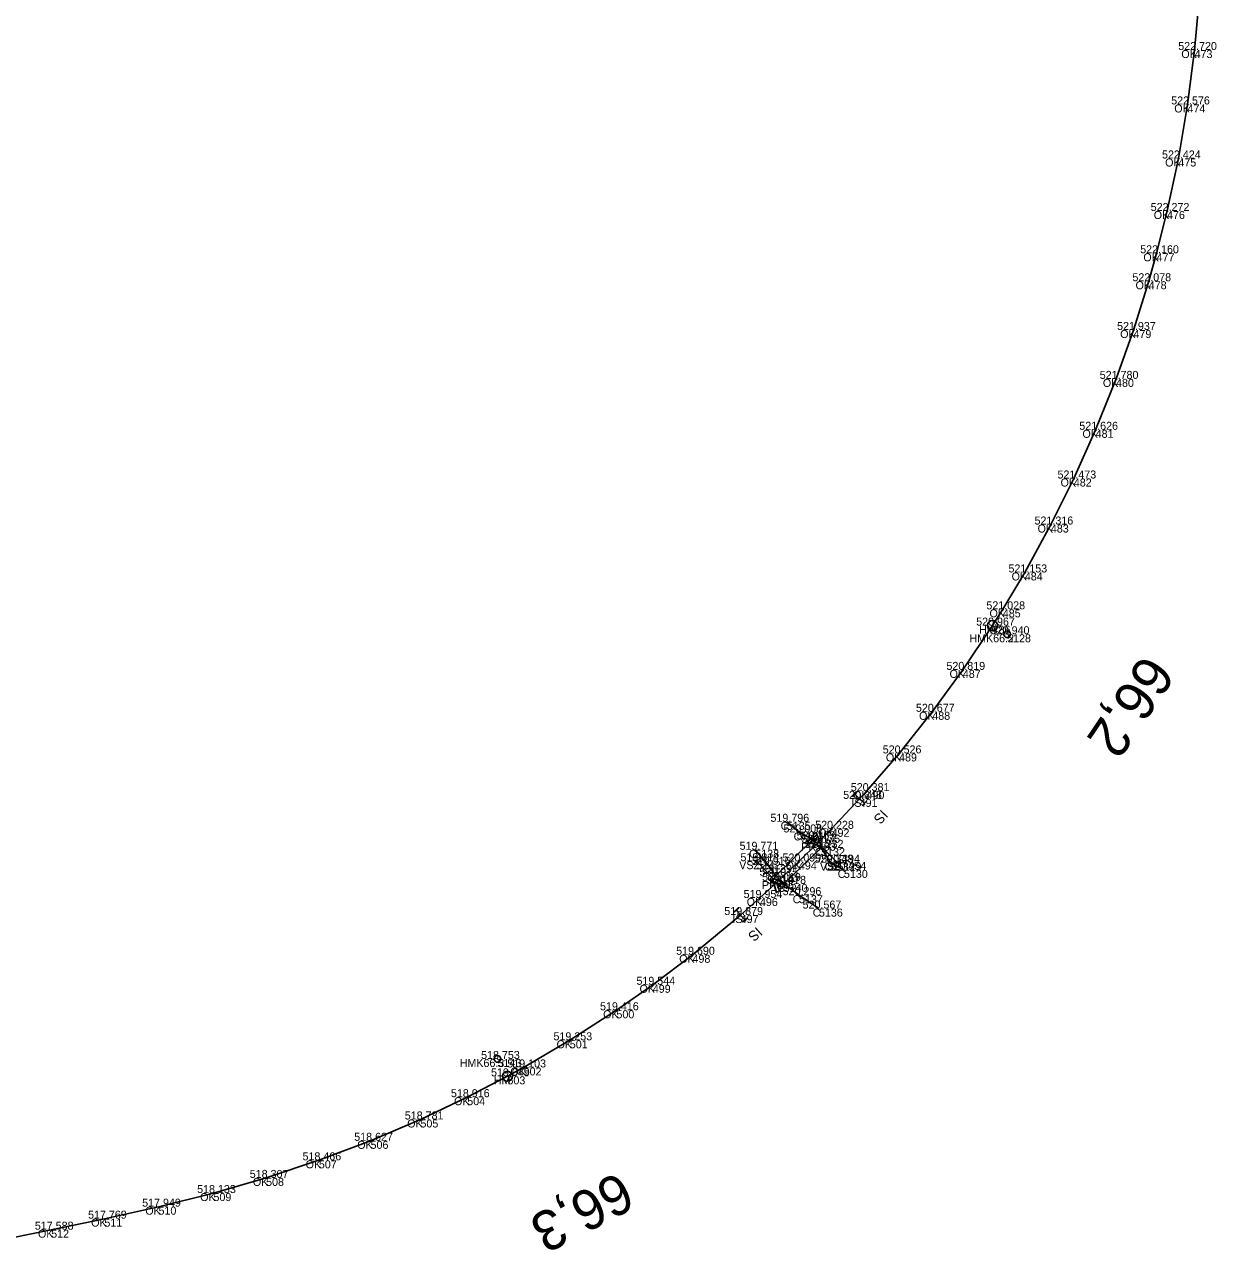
# Model space of a CAD drawing. Extents: x -621782 to -610392, y -1141853 to -1122321.
# Drawn here: x -621330.7 to -621152, y -1123404.2 to -1123220.4 of the extents above; entities that cross this region are included whole.
import ezdxf

# ---------------------------------------------------------------- set-up
doc = ezdxf.new("R2010")
doc.units = 0
for name, color, linetype in [('Vrstva 1', 7, 'Continuous'), ('Vrstva 3', 7, 'Continuous'), ('Vrstva 4', 7, 'Continuous'), ('Vrstva 51', 7, 'Continuous'), ('Vrstva 60', 7, 'Continuous'), ('Vrstva 61', 7, 'Continuous'), ('Vrstva 62', 7, 'Continuous'), ('Vrstva 7', 7, 'Continuous')]:
    doc.layers.add(name, color=color, linetype=linetype)

msp = doc.modelspace()

# ---------------------------------------------------------------- linework, layer by layer
at = {"layer": 'Vrstva 1'}
msp.add_lwpolyline([(-621154.6, -1123216.63), (-621155.27, -1123224.26), (-621156.33, -1123232.42), (-621157.7, -1123240.52), (-621159.4, -1123248.39), (-621160.97, -1123254.73), (-621162.14, -1123258.92), (-621164.43, -1123266.23), (-621167.04, -1123273.56), (-621170.1, -1123281.19), (-621173.37, -1123288.49), (-621176.81, -1123295.39), (-621180.72, -1123302.57), (-621184.02, -1123308.1), (-621185.56, -1123310.54), (-621190.01, -1123317.18), (-621194.59, -1123323.46), (-621199.57, -1123329.7), (-621204.45, -1123335.35), (-621205.49, -1123336.51), (-621209.69, -1123341), (-621211.75, -1123343.09), (-621214.59, -1123345.9), (-621217.64, -1123348.82), (-621220.43, -1123351.37), (-621223.32, -1123353.92), (-621230.54, -1123359.88), (-621236.49, -1123364.38), (-621241.94, -1123368.2), (-621248.93, -1123372.7), (-621255.85, -1123376.77), (-621258.28, -1123378.1), (-621264.3, -1123381.23), (-621271.32, -1123384.57), (-621278.8, -1123387.77), (-621286.55, -1123390.69), (-621294.46, -1123393.33), (-621302.35, -1123395.6), (-621310.59, -1123397.64), (-621318.7, -1123399.44), (-621326.68, -1123401.09), (-621335.56, -1123402.89)], dxfattribs=at)
at = {"layer": 'Vrstva 3'}
for p, q in [((-621205.88, -1123335.46), (-621206.56, -1123336.19)), ((-621204.76, -1123337.19), (-621206.22, -1123335.82)), ((-621204.42, -1123336.82), (-621205.1, -1123337.55)), ((-621223.61, -1123352.84), (-621224.36, -1123353.51)), ((-621222.66, -1123354.67), (-621223.98, -1123353.17)), ((-621222.28, -1123354.34), (-621223.03, -1123355))]:
    msp.add_line(p, q, dxfattribs=at)
at = {"layer": 'Vrstva 4'}
for p, q in [((-621212.26, -1123342.96), (-621212.26, -1123342.47)), ((-621220.32, -1123345.33), (-621221.47, -1123346.38)), ((-621209.33, -1123346.64), (-621208.24, -1123345.53)), ((-621217.6, -1123349.16), (-621217.62, -1123349.65))]:
    msp.add_line(p, q, dxfattribs=at)
for points in [[(-621208.78, -1123346.08), (-621211.26, -1123343.65), (-621213.39, -1123342.95), (-621211.99, -1123341.52), (-621211.26, -1123343.65)], [(-621211.75, -1123343.09), (-621214.59, -1123345.9), (-621217.64, -1123348.82)], [(-621220.9, -1123345.86), (-621218.55, -1123348.42), (-621216.47, -1123349.24), (-621217.94, -1123350.59), (-621218.55, -1123348.42)]]:
    msp.add_lwpolyline(points, dxfattribs=at)
for centre in [(-621212.26, -1123342.71), (-621217.61, -1123349.41)]:
    msp.add_circle(centre, 0.248, dxfattribs=at)
at = {"layer": 'Vrstva 51'}
for points in [[(-621221.12, -1123344.14), (-621219.19, -1123346.4), (-621218.05, -1123348.03), (-621212.48, -1123342.58), (-621214.45, -1123341.54), (-621216.4, -1123339.95)], [(-621207.83, -1123347.15), (-621209.79, -1123346.08), (-621211.25, -1123343.86), (-621216.87, -1123349.25), (-621214.57, -1123350.95), (-621211.58, -1123352.96)]]:
    msp.add_lwpolyline(points, dxfattribs=at)
at = {"layer": 'Vrstva 60'}
for p, q in [((-621155.27, -1123224.26), (-621155.27, -1123224.26)), ((-621156.33, -1123232.42), (-621156.33, -1123232.42)), ((-621157.7, -1123240.52), (-621157.7, -1123240.52)), ((-621159.4, -1123248.39), (-621159.4, -1123248.39)), ((-621160.97, -1123254.73), (-621160.97, -1123254.73)), ((-621162.14, -1123258.92), (-621162.14, -1123258.92)), ((-621164.43, -1123266.23), (-621164.43, -1123266.23)), ((-621167.04, -1123273.56), (-621167.04, -1123273.56)), ((-621170.1, -1123281.19), (-621170.1, -1123281.19)), ((-621173.37, -1123288.49), (-621173.37, -1123288.49)), ((-621176.81, -1123295.39), (-621176.81, -1123295.39)), ((-621180.72, -1123302.57), (-621180.72, -1123302.57)), ((-621184.02, -1123308.1), (-621184.02, -1123308.1)), ((-621185.56, -1123310.54), (-621185.56, -1123310.54)), ((-621183.37, -1123311.84), (-621183.37, -1123311.84)), ((-621190.01, -1123317.18), (-621190.01, -1123317.18)), ((-621194.59, -1123323.46), (-621194.59, -1123323.46)), ((-621199.57, -1123329.7), (-621199.57, -1123329.7)), ((-621205.49, -1123336.51), (-621205.49, -1123336.51)), ((-621204.45, -1123335.35), (-621204.45, -1123335.35)), ((-621216.4, -1123339.95), (-621216.4, -1123339.95)), ((-621214.45, -1123341.54), (-621214.45, -1123341.54)), ((-621209.69, -1123341), (-621209.69, -1123341)), ((-621212.48, -1123342.58), (-621212.48, -1123342.58)), ((-621211.75, -1123343.09), (-621211.75, -1123343.09)), ((-621211.25, -1123343.86), (-621211.25, -1123343.86)), ((-621221.12, -1123344.14), (-621221.12, -1123344.14)), ((-621220.9, -1123345.86), (-621220.9, -1123345.86)), ((-621219.19, -1123346.4), (-621219.19, -1123346.4)), ((-621214.59, -1123345.9), (-621214.59, -1123345.9)), ((-621209.79, -1123346.08), (-621209.79, -1123346.08)), ((-621208.78, -1123346.08), (-621208.78, -1123346.08)), ((-621207.83, -1123347.15), (-621207.83, -1123347.15)), ((-621218.05, -1123348.03), (-621218.05, -1123348.03)), ((-621217.64, -1123348.82), (-621217.64, -1123348.82)), ((-621216.87, -1123349.25), (-621216.87, -1123349.25)), ((-621214.57, -1123350.95), (-621214.57, -1123350.95)), ((-621220.43, -1123351.37), (-621220.43, -1123351.37)), ((-621211.58, -1123352.96), (-621211.58, -1123352.96)), ((-621223.32, -1123353.92), (-621223.32, -1123353.92)), ((-621230.54, -1123359.88), (-621230.54, -1123359.88)), ((-621236.49, -1123364.38), (-621236.49, -1123364.38)), ((-621241.94, -1123368.2), (-621241.94, -1123368.2)), ((-621248.93, -1123372.7), (-621248.93, -1123372.7)), ((-621259.77, -1123375.5), (-621259.77, -1123375.5)), ((-621255.85, -1123376.77), (-621255.85, -1123376.77)), ((-621258.28, -1123378.1), (-621258.28, -1123378.1)), ((-621264.3, -1123381.23), (-621264.3, -1123381.23)), ((-621271.32, -1123384.57), (-621271.32, -1123384.57)), ((-621278.8, -1123387.77), (-621278.8, -1123387.77)), ((-621286.55, -1123390.69), (-621286.55, -1123390.69)), ((-621294.46, -1123393.33), (-621294.46, -1123393.33)), ((-621302.35, -1123395.6), (-621302.35, -1123395.6)), ((-621310.59, -1123397.64), (-621310.59, -1123397.64)), ((-621318.7, -1123399.44), (-621318.7, -1123399.44)), ((-621326.68, -1123401.09), (-621326.68, -1123401.09))]:
    msp.add_line(p, q, dxfattribs=at)
at = {"layer": 'Vrstva 7'}
for p, q in [((-621183.34, -1123311.8), (-621183.4, -1123311.89)), ((-621259.73, -1123375.47), (-621259.82, -1123375.52))]:
    msp.add_line(p, q, dxfattribs=at)
for centre, radius in [((-621185.56, -1123310.54), 0.75), ((-621183.37, -1123311.84), 0.5), ((-621259.77, -1123375.5), 0.5), ((-621258.28, -1123378.1), 0.75)]:
    msp.add_circle(centre, radius, dxfattribs=at)

# ---------------------------------------------------------------- texts
at = {"layer": 'Vrstva 3'}
for rotation, p in [(226.9113, (-621202.2, -1123338.03)), (221.4636, (-621220.91, -1123355.63))]:
    msp.add_text('IS', height=1.5, rotation=rotation, dxfattribs=at).set_placement(p)
at = {"layer": 'Vrstva 60'}
for s, p in [('473', (-621155.27, -1123225.46)), ('474', (-621156.33, -1123233.62)), ('475', (-621157.7, -1123241.72)), ('476', (-621159.4, -1123249.59)), ('477', (-621160.97, -1123255.93)), ('478', (-621162.14, -1123260.12)), ('479', (-621164.43, -1123267.43)), ('480', (-621167.04, -1123274.76)), ('481', (-621170.1, -1123282.39)), ('482', (-621173.37, -1123289.69)), ('483', (-621176.81, -1123296.59)), ('484', (-621180.72, -1123303.77)), ('485', (-621184.02, -1123309.3)), ('486', (-621185.56, -1123311.74)), ('5128', (-621183.37, -1123313.04)), ('487', (-621190.01, -1123318.38)), ('488', (-621194.59, -1123324.66)), ('489', (-621199.57, -1123330.9)), ('491', (-621205.49, -1123337.71)), ('490', (-621204.45, -1123336.55)), ('5135', (-621216.4, -1123341.15)), ('5134', (-621214.45, -1123342.74)), ('492', (-621209.69, -1123342.2)), ('5131', (-621212.48, -1123343.78)), ('493', (-621211.75, -1123344.29)), ('5132', (-621211.25, -1123345.06)), ('5138', (-621221.12, -1123345.34)), ('5142', (-621220.9, -1123347.05)), ('5139', (-621219.19, -1123347.6)), ('494', (-621214.59, -1123347.1)), ('5133', (-621209.79, -1123347.28)), ('5129', (-621208.78, -1123347.28)), ('5130', (-621207.83, -1123348.35)), ('5141', (-621218.05, -1123349.23)), ('495', (-621217.64, -1123350.02)), ('5140', (-621216.87, -1123350.45)), ('5137', (-621214.57, -1123352.15)), ('496', (-621220.43, -1123352.57)), ('5136', (-621211.58, -1123354.16)), ('497', (-621223.32, -1123355.12)), ('498', (-621230.54, -1123361.08)), ('499', (-621236.49, -1123365.58)), ('500', (-621241.94, -1123369.4)), ('501', (-621248.93, -1123373.9)), ('5143', (-621259.77, -1123376.7)), ('502', (-621255.85, -1123377.97)), ('503', (-621258.28, -1123379.3)), ('504', (-621264.3, -1123382.43)), ('505', (-621271.32, -1123385.77)), ('506', (-621278.8, -1123388.97)), ('507', (-621286.55, -1123391.89)), ('508', (-621294.46, -1123394.53)), ('509', (-621302.35, -1123396.8)), ('510', (-621310.59, -1123398.84)), ('511', (-621318.7, -1123400.64)), ('512', (-621326.68, -1123402.29))]:
    msp.add_text(s, height=1.2, dxfattribs=at).set_placement(p)
at = {"layer": 'Vrstva 61'}
for s, p in [('522.720', (-621157.72, -1123224.26)), ('522.576', (-621158.78, -1123232.42)), ('522.424', (-621160.15, -1123240.52)), ('522.272', (-621161.85, -1123248.39)), ('522.160', (-621163.42, -1123254.73)), ('522.078', (-621164.59, -1123258.92)), ('521.937', (-621166.89, -1123266.23)), ('521.780', (-621169.49, -1123273.56)), ('521.626', (-621172.55, -1123281.19)), ('521.473', (-621175.82, -1123288.49)), ('521.316', (-621179.26, -1123295.39)), ('521.153', (-621183.17, -1123302.57)), ('521.028', (-621186.48, -1123308.1)), ('520.967', (-621188.01, -1123310.54)), ('520.940', (-621185.82, -1123311.84)), ('520.819', (-621192.47, -1123317.18)), ('520.677', (-621197.04, -1123323.46)), ('520.526', (-621202.02, -1123329.7)), ('520.381', (-621206.81, -1123335.35)), ('520.348', (-621207.95, -1123336.51)), ('519.796', (-621218.85, -1123339.95)), ('520.228', (-621212.15, -1123341)), ('520.008', (-621216.9, -1123341.54)), ('520.153', (-621214.93, -1123342.58)), ('520.175', (-621214.21, -1123343.09)), ('519.771', (-621223.48, -1123344.14)), ('520.232', (-621213.7, -1123343.86)), ('519.814', (-621223.35, -1123345.86)), ('519.916', (-621221.64, -1123346.4)), ('520.099', (-621217.05, -1123345.9)), ('520.348', (-621212.24, -1123346.08)), ('520.394', (-621211.23, -1123346.08)), ('520.015', (-621220.51, -1123348.03)), ('520.019', (-621220.1, -1123348.82)), ('520.454', (-621210.28, -1123347.15)), ('520.078', (-621219.32, -1123349.25)), ('519.954', (-621222.88, -1123351.37)), ('520.296', (-621217.02, -1123350.95)), ('519.879', (-621225.77, -1123353.92)), ('520.567', (-621214.03, -1123352.96)), ('519.690', (-621232.99, -1123359.88)), ('519.544', (-621238.94, -1123364.38)), ('519.416', (-621244.4, -1123368.2)), ('519.253', (-621251.38, -1123372.7)), ('518.753', (-621262.23, -1123375.5)), ('519.049', (-621260.74, -1123378.1)), ('519.103', (-621258.3, -1123376.77)), ('518.916', (-621266.75, -1123381.23)), ('518.781', (-621273.67, -1123384.57)), ('518.627', (-621281.25, -1123387.77)), ('518.466', (-621289, -1123390.69)), ('518.307', (-621296.91, -1123393.33)), ('518.133', (-621304.8, -1123395.6)), ('517.949', (-621313.04, -1123397.64)), ('517.769', (-621321.15, -1123399.44)), ('517.588', (-621329.13, -1123401.09))]:
    msp.add_text(s, height=1.2, dxfattribs=at).set_placement(p)
at = {"layer": 'Vrstva 62'}
for s, p in [('OK', (-621157.26, -1123225.46)), ('OK', (-621158.31, -1123233.62)), ('OK', (-621159.68, -1123241.72)), ('OK', (-621161.39, -1123249.59)), ('OK', (-621162.95, -1123255.93)), ('OK', (-621164.12, -1123260.12)), ('OK', (-621166.42, -1123267.43)), ('OK', (-621169.02, -1123274.76)), ('OK', (-621172.08, -1123282.39)), ('OK', (-621175.36, -1123289.69)), ('OK', (-621178.8, -1123296.59)), ('OK', (-621182.7, -1123303.77)), ('OK', (-621186.01, -1123309.3)), ('HM', (-621187.59, -1123311.74)), ('HMK66.2', (-621189.03, -1123313.04)), ('OK', (-621192, -1123318.38)), ('OK', (-621196.57, -1123324.66)), ('OK', (-621201.55, -1123330.9)), ('IS', (-621206.72, -1123337.71)), ('OK', (-621206.44, -1123336.55)), ('C', (-621217.33, -1123341.15)), ('C', (-621215.38, -1123342.74)), ('OK', (-621211.68, -1123342.2)), ('PRJ', (-621214.24, -1123344.29)), ('C', (-621213.42, -1123343.78)), ('C', (-621212.19, -1123345.06)), ('C', (-621222.06, -1123345.34)), ('VSZ', (-621223.54, -1123347.05)), ('C', (-621220.12, -1123347.6)), ('OK', (-621216.58, -1123347.1)), ('VSZ', (-621211.42, -1123347.28)), ('C', (-621210.72, -1123347.28)), ('C', (-621208.77, -1123348.35)), ('PRJ', (-621220.13, -1123350.02)), ('C', (-621218.99, -1123349.23)), ('C', (-621217.81, -1123350.45)), ('C', (-621215.51, -1123352.15)), ('OK', (-621222.41, -1123352.57)), ('C', (-621212.51, -1123354.16)), ('IS', (-621224.55, -1123355.12)), ('OK', (-621232.53, -1123361.08)), ('OK', (-621238.47, -1123365.58)), ('OK', (-621243.93, -1123369.4)), ('OK', (-621250.91, -1123373.9)), ('HMK66.3', (-621265.44, -1123376.7)), ('OK', (-621257.83, -1123377.97)), ('HM', (-621260.32, -1123379.3)), ('OK', (-621266.28, -1123382.43)), ('OK', (-621273.3, -1123385.77)), ('OK', (-621280.79, -1123388.97)), ('OK', (-621288.53, -1123391.89)), ('OK', (-621296.44, -1123394.53)), ('OK', (-621304.34, -1123396.8)), ('OK', (-621312.57, -1123398.84)), ('OK', (-621320.68, -1123400.64)), ('OK', (-621328.66, -1123402.29))]:
    msp.add_text(s, height=1.2, dxfattribs=at).set_placement(p)
at = {"layer": 'Vrstva 7'}
for s, rotation, p in [('66,2', 236.1211, (-621162.92, -1123314.57)), ('66,3', 207.4948, (-621241.49, -1123392.25))]:
    msp.add_text(s, height=6, rotation=rotation, dxfattribs=at).set_placement(p)

doc.saveas('drawing.dxf')
